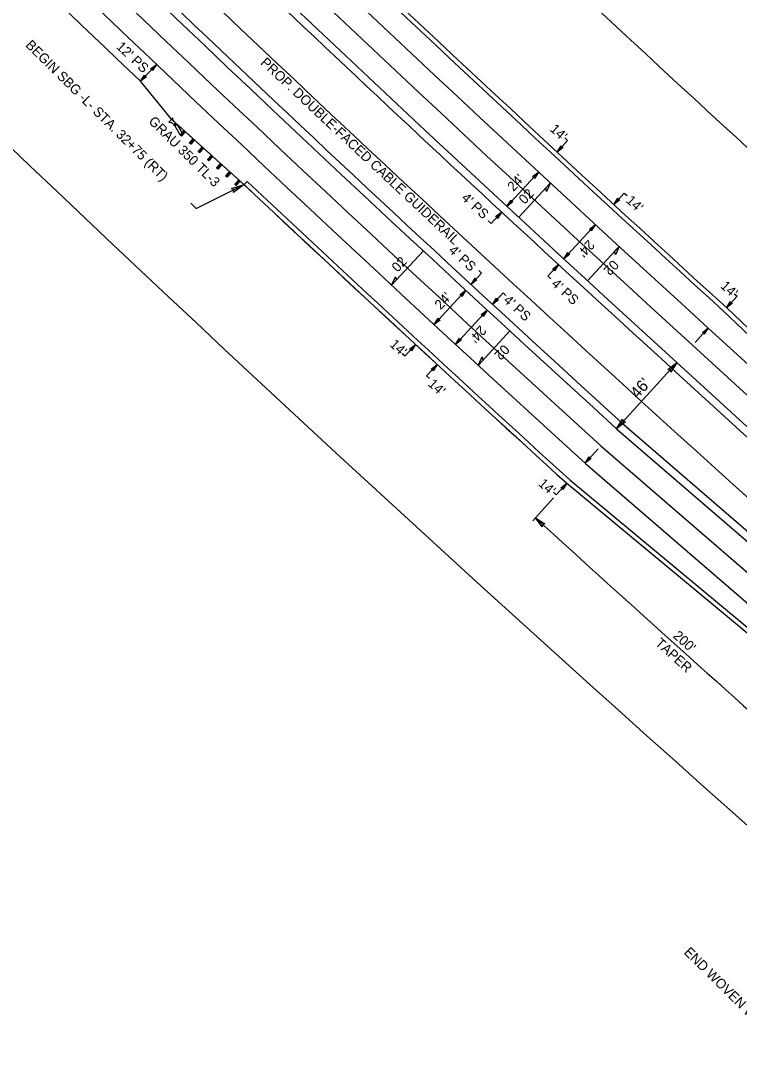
# Model space of a CAD drawing. Extents: x 1602193 to 1605074, y 908180 to 910630.
# Drawn here: x 1603654 to 1604023, y 908242 to 908781 of the extents above; entities that cross this region are included whole.
import ezdxf

# ---------------------------------------------------------------- set-up
doc = ezdxf.new("R2010")
doc.units = 0
for name, color, linetype in [('Prop Cable Guiderail Double Face', 7, 'Continuous'), ('Prop Conc Shoulder Berm Gutter', 7, 'Continuous'), ('Prop Dimension', 7, 'Continuous'), ('Prop Dimension Text', 7, 'Continuous'), ('Prop DSN Text', 7, 'Continuous'), ('Prop EOT', 7, 'Continuous'), ('Prop Fence Woven Wire', 7, 'Continuous'), ('Prop Guardrail', 7, 'Continuous'), ('Prop Guardrail Anchor Unit CELL', 7, 'Continuous'), ('Prop Lane Lines', 7, 'Continuous'), ('Prop Paved Shoulder', 7, 'Continuous'), ('Prop Superelevation  Arrow CELL', 7, 'Continuous'), ('Prop Superelevation Label', 7, 'Continuous'), ('Prop Terminator CELL', 7, 'Continuous')]:
    doc.layers.add(name, color=color, linetype=linetype)

msp = doc.modelspace()

# ---------------------------------------------------------------- linework, layer by layer
at = {"layer": 'Prop Cable Guiderail Double Face'}
msp.add_arc((1613646.31, 919202), 14362.86, 225.366604, 228.628709, dxfattribs=at)
at = {"layer": 'Prop Conc Shoulder Berm Gutter'}
for p, q in [((1604016.5, 908633.39), (1604161.04, 908495.7)), ((1603934.31, 908543.23), (1604088.67, 908415.14))]:
    msp.add_line(p, q, dxfattribs=at)
for radius, start, end in [(14297.86, 225.07288, 227.661141), (14419.86, 226.763228, 227.66104)]:
    msp.add_arc((1613646.31, 919202), radius, start, end, dxfattribs=at)
at = {"layer": 'Prop Dimension'}
for p, q in [((1604016.48, 908633.4), (1604021.87, 908639.32)), ((1604000.31, 908615.66), (1604007.05, 908623.06)), ((1603990.88, 908605.32), (1603959.9, 908571.31)), ((1603943.74, 908553.57), (1603950.47, 908560.97)), ((1603928.92, 908537.31), (1603934.31, 908543.23)), ((1603927.57, 908535.83), (1603916.82, 908524.03))]:
    msp.add_line(p, q, dxfattribs=at)
msp.add_arc((1613646.31, 919202), 14443.82, 227.66104, 228.45675, dxfattribs=at)
at = {"layer": 'Prop Dimension Text'}
for p, q in [((1603715.22, 908749.81), (1603723.49, 908758.51)), ((1603934.77, 908719.34), (1603929.34, 908713.46)), ((1603933.3, 908720.7), (1603934.77, 908719.34)), ((1603903.57, 908685.54), (1603919.86, 908703.16)), ((1603963.9, 908692.42), (1603958.49, 908686.54)), ((1603963.9, 908692.42), (1603965.37, 908691.07)), ((1603900.82, 908682.63), (1603895.39, 908676.76)), ((1603893.92, 908678.12), (1603895.39, 908676.76)), ((1603932.76, 908658.57), (1603949.01, 908676.23)), ((1603930.05, 908655.63), (1603924.63, 908649.74)), ((1603890.53, 908651.28), (1603885.11, 908645.4)), ((1603889.06, 908652.63), (1603890.53, 908651.28)), ((1603924.63, 908649.74), (1603926.11, 908648.39)), ((1603866.13, 908624.81), (1603882.41, 908642.44)), ((1603901.58, 908641.08), (1603896.15, 908635.19)), ((1603901.58, 908641.08), (1603903.05, 908639.72)), ((1604020.39, 908640.66), (1604021.87, 908639.32)), ((1603877.19, 908614.6), (1603893.45, 908632.25)), ((1603856.61, 908614.54), (1603851.19, 908608.66)), ((1603849.72, 908610.02), (1603851.19, 908608.66)), ((1603867.69, 908604.31), (1603862.27, 908598.42)), ((1603862.27, 908598.42), (1603863.74, 908597.07)), ((1603927.44, 908538.66), (1603928.92, 908537.31))]:
    msp.add_line(p, q, dxfattribs=at)
at = {"layer": 'Prop DSN Text'}
for p, q in [((1603743.85, 908684.38), (1603768.49, 908696.71)), ((1603741.02, 908687.18), (1603743.85, 908684.38))]:
    msp.add_line(p, q, dxfattribs=at)
for points in [[(1603720.39, 908756.21), (1603723.49, 908758.51), (1603721.35, 908755.29), (1603721.19, 908756.09)], [(1603718.32, 908752.11), (1603715.22, 908749.81), (1603717.36, 908753.03), (1603717.52, 908752.23)], [(1603932.41, 908715.8), (1603929.34, 908713.46), (1603931.43, 908716.71), (1603931.61, 908715.91)], [(1603916.79, 908700.82), (1603919.86, 908703.16), (1603917.77, 908699.92), (1603917.6, 908700.71)], [(1603906.64, 908687.88), (1603903.57, 908685.54), (1603905.66, 908688.79), (1603905.83, 908687.99)], [(1603961.55, 908688.88), (1603958.49, 908686.54), (1603960.57, 908689.79), (1603960.74, 908688.99)], [(1603897.75, 908680.3), (1603900.82, 908682.63), (1603898.73, 908679.39), (1603898.55, 908680.19)], [(1603945.94, 908673.89), (1603949.01, 908676.23), (1603946.93, 908672.98), (1603946.75, 908673.78)], [(1603935.83, 908660.92), (1603932.76, 908658.57), (1603934.84, 908661.82), (1603935.02, 908661.02)], [(1603926.99, 908653.28), (1603930.05, 908655.63), (1603927.97, 908652.38), (1603927.79, 908653.17)], [(1603888.18, 908647.74), (1603885.11, 908645.4), (1603887.2, 908648.64), (1603887.37, 908647.85)], [(1603879.34, 908640.1), (1603882.41, 908642.44), (1603880.32, 908639.2), (1603880.15, 908639.99)], [(1603899.22, 908637.54), (1603896.15, 908635.19), (1603898.24, 908638.44), (1603898.41, 908637.65)], [(1603890.38, 908629.9), (1603893.45, 908632.25), (1603891.36, 908629), (1603891.19, 908629.79)], [(1604019.53, 908635.77), (1604016.48, 908633.4), (1604018.55, 908636.66), (1604018.72, 908635.87)], [(1603869.2, 908627.15), (1603866.13, 908624.81), (1603868.22, 908628.06), (1603868.39, 908627.26)], [(1604004, 908620.69), (1604007.05, 908623.06), (1604004.98, 908619.8), (1604004.8, 908620.59)], [(1603880.25, 908616.94), (1603877.19, 908614.6), (1603879.27, 908617.84), (1603879.45, 908617.05)], [(1603853.55, 908612.2), (1603856.61, 908614.54), (1603854.53, 908611.29), (1603854.35, 908612.09)], [(1603986.3, 908601.77), (1603990.88, 908605.32), (1603987.78, 908600.43), (1603987.52, 908601.62)], [(1603864.63, 908601.96), (1603867.69, 908604.31), (1603865.61, 908601.06), (1603865.43, 908601.85)], [(1603964.48, 908574.86), (1603959.9, 908571.31), (1603963, 908576.2), (1603963.27, 908575.01)], [(1603946.79, 908555.93), (1603943.74, 908553.57), (1603945.81, 908556.83), (1603945.98, 908556.04)], [(1603931.26, 908540.86), (1603934.31, 908543.23), (1603932.24, 908539.97), (1603932.06, 908540.76)], [(1603921.71, 908520.93), (1603918.17, 908525.51), (1603923.06, 908522.41), (1603921.87, 908522.14)]]:
    msp.add_lwpolyline(points, close=True, dxfattribs=at)
at = {"layer": 'Prop EOT'}
for p, q in [((1604007.07, 908623.04), (1604227.69, 908421.16)), ((1603990.88, 908605.32), (1604211.9, 908403.08)), ((1603959.9, 908571.31), (1604187.27, 908374.89)), ((1603943.97, 908553.36), (1604171.48, 908356.82))]:
    msp.add_line(p, q, dxfattribs=at)
for radius, start, end in [(14311.86, 219.480877, 227.661141), (14335.86, 219.480979, 227.66104), (14381.86, 219.480979, 227.66104), (14405.86, 219.479716, 227.662303)]:
    msp.add_arc((1613646.31, 919202), radius, start, end, dxfattribs=at)
at = {"layer": 'Prop Fence Woven Wire'}
for centre, radius, start, end in [((1613600.28, 919154.72), 14163.95, 224.683047, 227.268962), ((1613603.09, 919154.06), 14423.95, 224.073496, 229.063445), ((1613600.28, 919154.72), 14163.95, 227.268962, 228.788844)]:
    msp.add_arc(centre, radius, start, end, dxfattribs=at)
at = {"layer": 'Prop Guardrail'}
for p, q in [((1604161.04, 908495.7), (1604016.5, 908633.39)), ((1603934.31, 908543.23), (1604088.67, 908415.14))]:
    msp.add_line(p, q, dxfattribs=at)
for radius, start, end in [(14297.86, 225.07288, 227.661141), (14419.86, 226.762396, 227.66104)]:
    msp.add_arc((1613646.31, 919202), radius, start, end, dxfattribs=at)
at = {"layer": 'Prop Guardrail Anchor Unit CELL'}
for p, q in [((1603731.8, 908730.99), (1603729.79, 908728.84)), ((1603732.07, 908729.55), (1603731.8, 908730.99)), ((1603733.56, 908728.16), (1603732.07, 908729.55)), ((1603729.79, 908728.84), (1603731.24, 908728.66)), ((1603731.24, 908728.66), (1603732.73, 908727.26)), ((1603733.27, 908728.52), (1603732.26, 908727.41)), ((1603732.26, 908727.41), (1603734.01, 908727.85)), ((1603733, 908726.74), (1603732.26, 908727.41)), ((1603733, 908726.74), (1603732.63, 908727.08)), ((1603732.73, 908727.26), (1603733.15, 908727.71)), ((1603733.27, 908728.52), (1603733, 908726.74)), ((1603734.01, 908727.85), (1603733, 908726.74)), ((1603735.59, 908722.3), (1603733, 908726.74)), ((1603733.15, 908727.71), (1603733.56, 908728.16)), ((1603768.34, 908696.86), (1603733.64, 908728.19)), ((1603736.62, 908723.43), (1603734.01, 908727.85)), ((1603737.65, 908724.57), (1603735.59, 908722.3)), ((1603738.39, 908723.9), (1603736.34, 908721.63)), ((1603738.39, 908723.9), (1603736.62, 908723.43)), ((1603737.36, 908722.76), (1603737.65, 908724.57)), ((1603735.59, 908722.3), (1603737.36, 908722.76)), ((1603736.34, 908721.63), (1603735.59, 908722.3)), ((1603736.62, 908723.43), (1603736.34, 908721.63)), ((1603737.36, 908722.76), (1603736.62, 908723.43)), ((1603742.32, 908720.35), (1603740.31, 908718.12)), ((1603740.31, 908718.12), (1603742.06, 908718.56)), ((1603743.07, 908719.68), (1603741.06, 908717.45)), ((1603741.32, 908719.23), (1603741.06, 908717.45)), ((1603743.07, 908719.68), (1603741.32, 908719.23)), ((1603742.06, 908718.56), (1603741.32, 908719.23)), ((1603742.06, 908718.56), (1603742.32, 908720.35)), ((1603741.06, 908717.45), (1603740.31, 908718.12)), ((1603747, 908716.12), (1603744.9, 908713.79)), ((1603744.9, 908713.79), (1603746.69, 908714.29)), ((1603745.64, 908713.12), (1603744.9, 908713.79)), ((1603747.74, 908715.45), (1603745.64, 908713.12)), ((1603745.95, 908714.96), (1603745.64, 908713.12)), ((1603747.74, 908715.45), (1603745.95, 908714.96)), ((1603746.69, 908714.29), (1603745.95, 908714.96)), ((1603746.69, 908714.29), (1603747, 908716.12)), ((1603751.68, 908711.9), (1603749.64, 908709.65)), ((1603749.64, 908709.65), (1603751.4, 908710.1)), ((1603750.38, 908708.98), (1603749.64, 908709.65)), ((1603752.42, 908711.23), (1603750.38, 908708.98)), ((1603750.66, 908710.77), (1603750.38, 908708.98)), ((1603752.42, 908711.23), (1603750.66, 908710.77)), ((1603751.4, 908710.1), (1603750.66, 908710.77)), ((1603751.4, 908710.1), (1603751.68, 908711.9)), ((1603752.42, 908711.23), (1603751.68, 908711.9)), ((1603756.35, 908707.68), (1603754.31, 908705.41)), ((1603756.07, 908705.88), (1603756.35, 908707.68)), ((1603754.31, 908705.41), (1603756.07, 908705.88)), ((1603755.05, 908704.74), (1603754.31, 908705.41)), ((1603757.1, 908707.01), (1603755.05, 908704.74)), ((1603755.33, 908706.55), (1603755.05, 908704.74)), ((1603757.1, 908707.01), (1603755.33, 908706.55)), ((1603756.07, 908705.88), (1603755.33, 908706.55)), ((1603761.03, 908703.45), (1603758.98, 908701.19)), ((1603761.77, 908702.78), (1603759.73, 908700.52)), ((1603760.01, 908702.32), (1603759.73, 908700.52)), ((1603761.77, 908702.78), (1603760.01, 908702.32)), ((1603760.75, 908701.65), (1603760.01, 908702.32)), ((1603760.75, 908701.65), (1603761.03, 908703.45)), ((1603758.98, 908701.19), (1603760.75, 908701.65)), ((1603759.73, 908700.52), (1603758.98, 908701.19)), ((1603765.71, 908699.23), (1603763.7, 908697)), ((1603763.7, 908697), (1603765.44, 908697.45)), ((1603764.44, 908696.33), (1603763.7, 908697)), ((1603766.45, 908698.56), (1603764.44, 908696.33)), ((1603764.7, 908698.12), (1603764.44, 908696.33)), ((1603765.71, 908699.23), (1603764.7, 908698.12)), ((1603764.7, 908698.12), (1603766.45, 908698.56)), ((1603765.44, 908697.45), (1603764.7, 908698.12)), ((1603765.44, 908697.45), (1603765.71, 908699.23)), ((1603766.45, 908698.56), (1603765.71, 908699.23))]:
    msp.add_line(p, q, dxfattribs=at)
at = {"layer": 'Prop Lane Lines'}
for p, q in [((1603998.97, 908614.19), (1604219.79, 908412.12)), ((1603951.82, 908562.44), (1604179.38, 908365.85))]:
    msp.add_line(p, q, dxfattribs=at)
for radius in [14323.86, 14393.86]:
    msp.add_arc((1613646.31, 919202), radius, 219.480979, 227.66104, dxfattribs=at)
at = {"layer": 'Prop Paved Shoulder'}
for p, q in [((1603731.22, 908730.37), (1603715.22, 908749.81)), ((1603768.34, 908696.86), (1603731.22, 908730.37)), ((1603768.49, 908696.71), (1603770.09, 908698.41)), ((1604014.91, 908631.68), (1604159.45, 908493.99)), ((1603988.19, 908602.36), (1604209.26, 908400.06)), ((1603962.56, 908574.31), (1604189.9, 908377.9)), ((1603935.84, 908544.99), (1604090.18, 908416.92))]:
    msp.add_line(p, q, dxfattribs=at)
for radius, start, end in [(14417.86, 224.337142, 226.464471), (14300.19, 225.07288, 227.661038), (14377.86, 225.269309, 227.660829), (14339.86, 225.77799, 227.66104), (14419.86, 226.762396, 226.763212), (14417.53, 226.763228, 227.660825)]:
    msp.add_arc((1613646.31, 919202), radius, start, end, dxfattribs=at)
at = {"layer": 'Prop Superelevation  Arrow CELL'}
for p, q in [((1603925.9, 908697.57), (1603909.6, 908679.96)), ((1603961.22, 908665), (1603944.98, 908647.33)), ((1603860.61, 908662.64), (1603844.28, 908645.06)), ((1603905.09, 908621.51), (1603888.84, 908603.86))]:
    msp.add_line(p, q, dxfattribs=at)
for points in [[(1603925.9, 908697.57), (1603923.94, 908693.25), (1603923.54, 908695.02)], [(1603961.22, 908665), (1603959.28, 908660.67), (1603958.87, 908662.45)], [(1603844.28, 908645.06), (1603846.24, 908649.37), (1603846.64, 908647.6)], [(1603888.84, 908603.86), (1603890.78, 908608.18), (1603891.19, 908606.41)]]:
    msp.add_lwpolyline(points, close=True, dxfattribs=at)
at = {"layer": 'Prop Terminator CELL'}
msp.add_lwpolyline([(1603761.93, 908694.73), (1603768.49, 908696.71), (1603762.96, 908692.6), (1603763.19, 908694.06)], close=True, dxfattribs=at)

# ---------------------------------------------------------------- texts
at = {"layer": 'Prop Cable Guiderail Double Face'}
msp.add_text('PROP. DOUBLE-FACED CABLE GUIDERAIL', height=5, rotation=316.9347, dxfattribs=at).set_placement((1603776.57, 908758.89))
at = {"layer": 'Prop Dimension Text'}
for s, height, rotation, p in [("12' PS", 5, 316.4645, (1603702.41, 908767.15)), ("14'", 5, 317.2269, (1603925.31, 908724.76)), ("24'", 5, 47.227, (1603906.95, 908692.89)), ("4' PS", 5, 317.1204, (1603879.8, 908689.42)), ("14'", 5, 317.3859, (1603964.41, 908688.06)), ("4' PS", 5, 317.2817, (1603873.26, 908662.46)), ("24'", 5, 227.3859, (1603945.48, 908668.71)), ("4' PS", 5, 317.3859, (1603926.01, 908645.23)), ("14'", 5, 317.661, (1604012.95, 908644.11)), ("24'", 5, 47.2818, (1603869.53, 908632.14)), ("4' PS", 5, 317.3417, (1603901.42, 908636.82)), ("24'", 5, 227.3421, (1603889.86, 908624.72)), ("14'", 5, 317.2817, (1603842.95, 908614.14)), ("14'", 5, 317.3417, (1603862.67, 908593.81)), ("46'", 6, 47.661, (1603970.71, 908586.33)), ("14'", 5, 317.661, (1603919.32, 908542.55)), ("200'", 5, 317.8587, (1603988.61, 908464.35)), ('TAPER', 5, 317.8572, (1603979.39, 908460.56))]:
    msp.add_text(s, height=height, rotation=rotation, dxfattribs=at).set_placement(p)
at = {"layer": 'Prop DSN Text'}
for s, p in [('BEGIN SBG -L- STA. 32+75 (RT)', (1603655.79, 908768.04)), ('END WOVEN WIRE FENCE', (1603994.18, 908301.87))]:
    msp.add_text(s, height=5, rotation=315.2976, dxfattribs=at).set_placement(p)
at = {"layer": 'Prop Guardrail Anchor Unit CELL'}
msp.add_text('GRAU 350 TL-3', height=5, rotation=315.2976, dxfattribs=at).set_placement((1603719.02, 908728.85))
at = {"layer": 'Prop Superelevation Label'}
for rotation, p in [(47.22, (1603912.75, 908686.31)), (47.1236, (1603847.45, 908651.4)), (227.4123, (1603957.87, 908658.4)), (227.3649, (1603901.74, 908614.92))]:
    msp.add_text('02', height=5, rotation=rotation, dxfattribs=at).set_placement(p)

doc.saveas('drawing.dxf')
